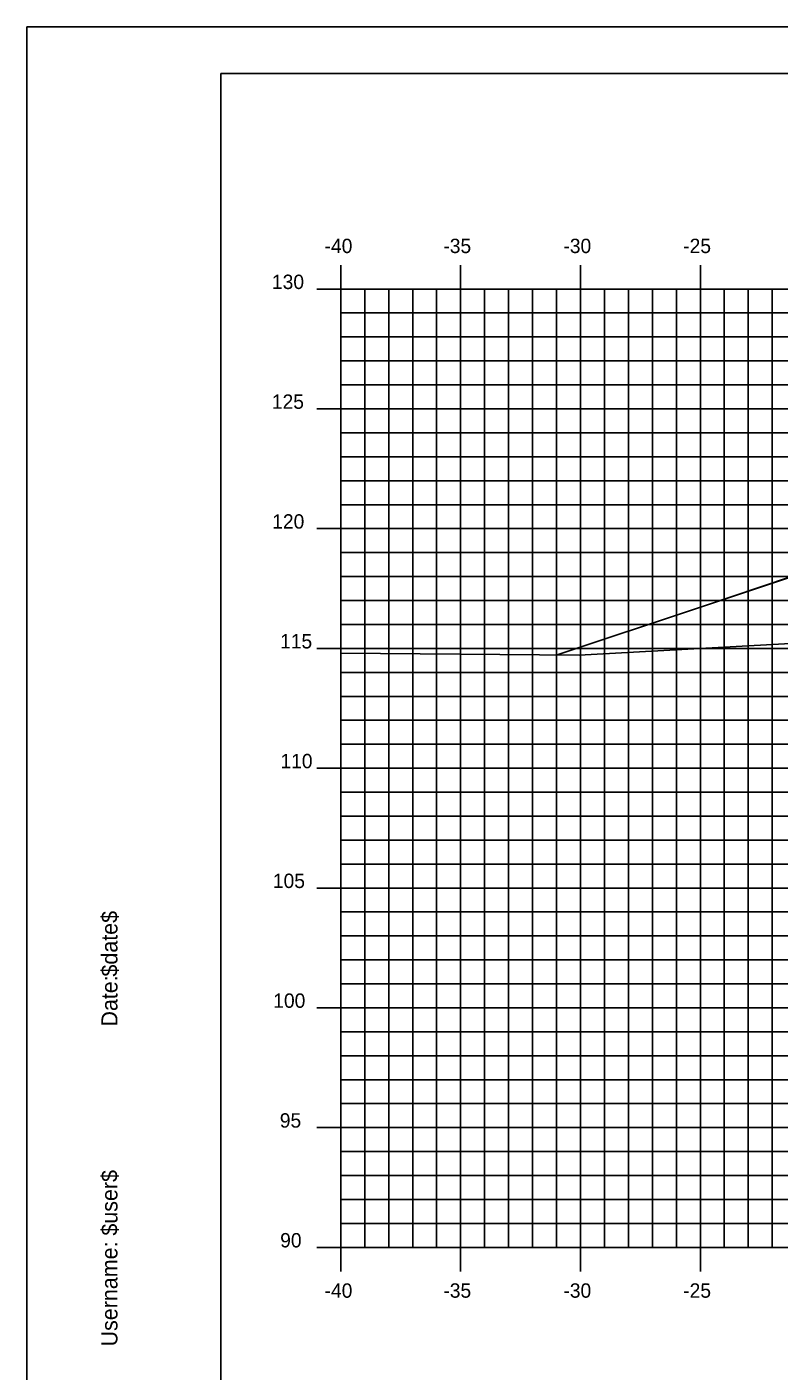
# Model space of a CAD drawing. Extents: x 850598 to 870284, y 366541 to 366651.
# Drawn here: x 852371.9 to 852403.2, y 366595.1 to 366651.2 of the extents above; entities that cross this region are included whole.
import ezdxf

# ---------------------------------------------------------------- set-up
doc = ezdxf.new("R2010")
doc.units = 0
for name, color, linetype in [('BORDER', 7, 'Continuous'), ('D_Roadway_Centerline', 7, 'Continuous'), ('D_Roadway_SlopeLines', 7, 'Continuous'), ('H_V ANNOTATION', 7, 'Continuous'), ('MAJOR', 7, 'Continuous'), ('MINOR', 7, 'Continuous'), ('PLOT BOUNDARY', 7, 'Continuous'), ('S_Roadway_Centerline', 7, 'Continuous')]:
    doc.layers.add(name, color=color, linetype=linetype)

msp = doc.modelspace()

# ---------------------------------------------------------------- linework, layer by layer
at = {"layer": 'BORDER'}
for p, q in [((852539.949, 366649.225), (852379.949, 366649.225)), ((852379.949, 366649.225), (852379.949, 366544.225))]:
    msp.add_line(p, q, dxfattribs=at)
at = {"layer": 'D_Roadway_Centerline'}
msp.add_lwpolyline([(852393.929, 366624.947), (852399.949, 366626.954), (852403.751, 366628.221), (852409.949, 366630.287), (852413.949, 366630.527), (852424.949, 366630.857), (852435.949, 366630.527), (852439.949, 366630.287), (852441.949, 366630.167), (852447.949, 366628.167), (852483.719, 366618.225), (852495.444, 366614.966), (852505.306, 366612.225), (852509.306, 366612.225)], dxfattribs=at)
at = {"layer": 'D_Roadway_SlopeLines'}
for points in [[(852413.949, 366630.527), (852409.949, 366630.287), (852399.949, 366626.954)], [(852399.949, 366626.954), (852393.929, 366624.947)]]:
    msp.add_lwpolyline(points, dxfattribs=at)
at = {"layer": 'MAJOR'}
for p, q in [((852384.949, 366641.227), (852384.949, 366640.225)), ((852384.949, 366641.227), (852384.949, 366640.225)), ((852389.949, 366641.227), (852389.949, 366640.225)), ((852389.949, 366641.227), (852389.949, 366640.225)), ((852394.949, 366641.227), (852394.949, 366640.225)), ((852394.949, 366641.227), (852394.949, 366640.225)), ((852399.949, 366641.227), (852399.949, 366640.225)), ((852399.949, 366641.227), (852399.949, 366640.225)), ((852383.947, 366640.225), (852384.949, 366640.225)), ((852383.947, 366640.225), (852384.949, 366640.225)), ((852384.949, 366640.225), (852524.949, 366640.225)), ((852384.949, 366600.225), (852384.949, 366640.225)), ((852384.949, 366600.225), (852384.949, 366640.225)), ((852384.949, 366640.225), (852524.949, 366640.225)), ((852384.949, 366640.225), (852524.949, 366640.225)), ((852384.949, 366600.225), (852384.949, 366640.225)), ((852384.949, 366600.225), (852384.949, 366640.225)), ((852384.949, 366640.225), (852524.949, 366640.225)), ((852389.949, 366600.225), (852389.949, 366640.225)), ((852389.949, 366600.225), (852389.949, 366640.225)), ((852394.949, 366600.225), (852394.949, 366640.225)), ((852394.949, 366600.225), (852394.949, 366640.225)), ((852399.949, 366600.225), (852399.949, 366640.225)), ((852399.949, 366600.225), (852399.949, 366640.225)), ((852383.947, 366635.225), (852384.949, 366635.225)), ((852383.947, 366635.225), (852384.949, 366635.225)), ((852384.949, 366635.225), (852524.949, 366635.225)), ((852384.949, 366635.225), (852524.949, 366635.225)), ((852383.947, 366630.225), (852384.949, 366630.225)), ((852383.947, 366630.225), (852384.949, 366630.225)), ((852384.949, 366630.225), (852524.949, 366630.225)), ((852384.949, 366630.225), (852524.949, 366630.225)), ((852383.947, 366625.225), (852384.949, 366625.225)), ((852383.947, 366625.225), (852384.949, 366625.225)), ((852384.949, 366625.225), (852524.949, 366625.225)), ((852384.949, 366625.225), (852524.949, 366625.225)), ((852383.947, 366620.225), (852384.949, 366620.225)), ((852383.947, 366620.225), (852384.949, 366620.225)), ((852384.949, 366620.225), (852524.949, 366620.225)), ((852384.949, 366620.225), (852524.949, 366620.225)), ((852383.947, 366615.225), (852384.949, 366615.225)), ((852383.947, 366615.225), (852384.949, 366615.225)), ((852384.949, 366615.225), (852524.949, 366615.225)), ((852384.949, 366615.225), (852524.949, 366615.225)), ((852383.947, 366610.225), (852384.949, 366610.225)), ((852383.947, 366610.225), (852384.949, 366610.225)), ((852384.949, 366610.225), (852524.949, 366610.225)), ((852384.949, 366610.225), (852524.949, 366610.225)), ((852383.947, 366605.225), (852384.949, 366605.225)), ((852383.947, 366605.225), (852384.949, 366605.225)), ((852384.949, 366605.225), (852524.949, 366605.225)), ((852384.949, 366605.225), (852524.949, 366605.225)), ((852383.947, 366600.225), (852384.949, 366600.225)), ((852383.947, 366600.225), (852384.949, 366600.225)), ((852384.949, 366600.225), (852524.949, 366600.225)), ((852384.949, 366600.225), (852524.949, 366600.225)), ((852384.949, 366599.223), (852384.949, 366600.225)), ((852384.949, 366600.225), (852524.949, 366600.225)), ((852384.949, 366600.225), (852524.949, 366600.225)), ((852384.949, 366599.223), (852384.949, 366600.225)), ((852389.949, 366599.223), (852389.949, 366600.225)), ((852389.949, 366599.223), (852389.949, 366600.225)), ((852394.949, 366599.223), (852394.949, 366600.225)), ((852394.949, 366599.223), (852394.949, 366600.225)), ((852399.949, 366599.223), (852399.949, 366600.225)), ((852399.949, 366599.223), (852399.949, 366600.225))]:
    msp.add_line(p, q, dxfattribs=at)
at = {"layer": 'MINOR'}
for p, q in [((852385.949, 366600.225), (852385.949, 366640.225)), ((852385.949, 366600.225), (852385.949, 366640.225)), ((852386.949, 366600.225), (852386.949, 366640.225)), ((852386.949, 366600.225), (852386.949, 366640.225)), ((852387.949, 366600.225), (852387.949, 366640.225)), ((852387.949, 366600.225), (852387.949, 366640.225)), ((852388.949, 366600.225), (852388.949, 366640.225)), ((852388.949, 366600.225), (852388.949, 366640.225)), ((852390.949, 366600.225), (852390.949, 366640.225)), ((852390.949, 366600.225), (852390.949, 366640.225)), ((852391.949, 366600.225), (852391.949, 366640.225)), ((852391.949, 366600.225), (852391.949, 366640.225)), ((852392.949, 366600.225), (852392.949, 366640.225)), ((852392.949, 366600.225), (852392.949, 366640.225)), ((852393.949, 366600.225), (852393.949, 366640.225)), ((852393.949, 366600.225), (852393.949, 366640.225)), ((852395.949, 366600.225), (852395.949, 366640.225)), ((852395.949, 366600.225), (852395.949, 366640.225)), ((852396.949, 366600.225), (852396.949, 366640.225)), ((852396.949, 366600.225), (852396.949, 366640.225)), ((852397.949, 366600.225), (852397.949, 366640.225)), ((852397.949, 366600.225), (852397.949, 366640.225)), ((852398.949, 366600.225), (852398.949, 366640.225)), ((852398.949, 366600.225), (852398.949, 366640.225)), ((852400.949, 366600.225), (852400.949, 366640.225)), ((852400.949, 366600.225), (852400.949, 366640.225)), ((852401.949, 366600.225), (852401.949, 366640.225)), ((852401.949, 366600.225), (852401.949, 366640.225)), ((852402.949, 366600.225), (852402.949, 366640.225)), ((852402.949, 366600.225), (852402.949, 366640.225)), ((852384.949, 366639.225), (852524.949, 366639.225)), ((852384.949, 366639.225), (852385.951, 366639.225)), ((852384.949, 366639.225), (852524.949, 366639.225)), ((852384.949, 366639.225), (852385.951, 366639.225)), ((852384.949, 366638.225), (852524.949, 366638.225)), ((852384.949, 366638.225), (852385.951, 366638.225)), ((852384.949, 366638.225), (852524.949, 366638.225)), ((852384.949, 366638.225), (852385.951, 366638.225)), ((852384.949, 366637.225), (852524.949, 366637.225)), ((852384.949, 366637.225), (852385.951, 366637.225)), ((852384.949, 366637.225), (852524.949, 366637.225)), ((852384.949, 366637.225), (852385.951, 366637.225)), ((852384.949, 366636.225), (852524.949, 366636.225)), ((852384.949, 366636.225), (852385.951, 366636.225)), ((852384.949, 366636.225), (852524.949, 366636.225)), ((852384.949, 366636.225), (852385.951, 366636.225)), ((852384.949, 366634.225), (852524.949, 366634.225)), ((852384.949, 366634.225), (852385.951, 366634.225)), ((852384.949, 366634.225), (852524.949, 366634.225)), ((852384.949, 366634.225), (852385.951, 366634.225)), ((852384.949, 366633.225), (852524.949, 366633.225)), ((852384.949, 366633.225), (852385.951, 366633.225)), ((852384.949, 366633.225), (852524.949, 366633.225)), ((852384.949, 366633.225), (852385.951, 366633.225)), ((852384.949, 366632.225), (852524.949, 366632.225)), ((852384.949, 366632.225), (852385.951, 366632.225)), ((852384.949, 366632.225), (852524.949, 366632.225)), ((852384.949, 366632.225), (852385.951, 366632.225)), ((852384.949, 366631.225), (852524.949, 366631.225)), ((852384.949, 366631.225), (852385.951, 366631.225)), ((852384.949, 366631.225), (852524.949, 366631.225)), ((852384.949, 366631.225), (852385.951, 366631.225)), ((852384.949, 366629.225), (852524.949, 366629.225)), ((852384.949, 366629.225), (852385.951, 366629.225)), ((852384.949, 366629.225), (852524.949, 366629.225)), ((852384.949, 366629.225), (852385.951, 366629.225)), ((852384.949, 366628.225), (852524.949, 366628.225)), ((852384.949, 366628.225), (852385.951, 366628.225)), ((852384.949, 366628.225), (852524.949, 366628.225)), ((852384.949, 366628.225), (852385.951, 366628.225)), ((852384.949, 366627.225), (852524.949, 366627.225)), ((852384.949, 366627.225), (852385.951, 366627.225)), ((852384.949, 366627.225), (852524.949, 366627.225)), ((852384.949, 366627.225), (852385.951, 366627.225)), ((852384.949, 366626.225), (852524.949, 366626.225)), ((852384.949, 366626.225), (852385.951, 366626.225)), ((852384.949, 366626.225), (852524.949, 366626.225)), ((852384.949, 366626.225), (852385.951, 366626.225)), ((852384.949, 366624.225), (852524.949, 366624.225)), ((852384.949, 366624.225), (852385.951, 366624.225)), ((852384.949, 366624.225), (852524.949, 366624.225)), ((852384.949, 366624.225), (852385.951, 366624.225)), ((852384.949, 366623.225), (852524.949, 366623.225)), ((852384.949, 366623.225), (852385.951, 366623.225)), ((852384.949, 366623.225), (852524.949, 366623.225)), ((852384.949, 366623.225), (852385.951, 366623.225)), ((852384.949, 366622.225), (852524.949, 366622.225)), ((852384.949, 366622.225), (852385.951, 366622.225)), ((852384.949, 366622.225), (852524.949, 366622.225)), ((852384.949, 366622.225), (852385.951, 366622.225)), ((852384.949, 366621.225), (852524.949, 366621.225)), ((852384.949, 366621.225), (852385.951, 366621.225)), ((852384.949, 366621.225), (852524.949, 366621.225)), ((852384.949, 366621.225), (852385.951, 366621.225)), ((852384.949, 366619.225), (852524.949, 366619.225)), ((852384.949, 366619.225), (852385.951, 366619.225)), ((852384.949, 366619.225), (852524.949, 366619.225)), ((852384.949, 366619.225), (852385.951, 366619.225)), ((852384.949, 366618.225), (852524.949, 366618.225)), ((852384.949, 366618.225), (852385.951, 366618.225)), ((852384.949, 366618.225), (852524.949, 366618.225)), ((852384.949, 366618.225), (852385.951, 366618.225)), ((852384.949, 366617.225), (852524.949, 366617.225)), ((852384.949, 366617.225), (852385.951, 366617.225)), ((852384.949, 366617.225), (852524.949, 366617.225)), ((852384.949, 366617.225), (852385.951, 366617.225)), ((852384.949, 366616.225), (852524.949, 366616.225)), ((852384.949, 366616.225), (852385.951, 366616.225)), ((852384.949, 366616.225), (852524.949, 366616.225)), ((852384.949, 366616.225), (852385.951, 366616.225)), ((852384.949, 366614.225), (852524.949, 366614.225)), ((852384.949, 366614.225), (852385.951, 366614.225)), ((852384.949, 366614.225), (852524.949, 366614.225)), ((852384.949, 366614.225), (852385.951, 366614.225)), ((852384.949, 366613.225), (852524.949, 366613.225)), ((852384.949, 366613.225), (852385.951, 366613.225)), ((852384.949, 366613.225), (852524.949, 366613.225)), ((852384.949, 366613.225), (852385.951, 366613.225)), ((852384.949, 366612.225), (852524.949, 366612.225)), ((852384.949, 366612.225), (852385.951, 366612.225)), ((852384.949, 366612.225), (852524.949, 366612.225)), ((852384.949, 366612.225), (852385.951, 366612.225)), ((852384.949, 366611.225), (852524.949, 366611.225)), ((852384.949, 366611.225), (852385.951, 366611.225)), ((852384.949, 366611.225), (852524.949, 366611.225)), ((852384.949, 366611.225), (852385.951, 366611.225)), ((852384.949, 366609.225), (852524.949, 366609.225)), ((852384.949, 366609.225), (852385.951, 366609.225)), ((852384.949, 366609.225), (852524.949, 366609.225)), ((852384.949, 366609.225), (852385.951, 366609.225)), ((852384.949, 366608.225), (852524.949, 366608.225)), ((852384.949, 366608.225), (852385.951, 366608.225)), ((852384.949, 366608.225), (852524.949, 366608.225)), ((852384.949, 366608.225), (852385.951, 366608.225)), ((852384.949, 366607.225), (852524.949, 366607.225)), ((852384.949, 366607.225), (852385.951, 366607.225)), ((852384.949, 366607.225), (852524.949, 366607.225)), ((852384.949, 366607.225), (852385.951, 366607.225)), ((852384.949, 366606.225), (852524.949, 366606.225)), ((852384.949, 366606.225), (852385.951, 366606.225)), ((852384.949, 366606.225), (852524.949, 366606.225)), ((852384.949, 366606.225), (852385.951, 366606.225)), ((852384.949, 366604.225), (852524.949, 366604.225)), ((852384.949, 366604.225), (852385.951, 366604.225)), ((852384.949, 366604.225), (852524.949, 366604.225)), ((852384.949, 366604.225), (852385.951, 366604.225)), ((852384.949, 366603.225), (852524.949, 366603.225)), ((852384.949, 366603.225), (852385.951, 366603.225)), ((852384.949, 366603.225), (852524.949, 366603.225)), ((852384.949, 366603.225), (852385.951, 366603.225)), ((852384.949, 366602.225), (852524.949, 366602.225)), ((852384.949, 366602.225), (852385.951, 366602.225)), ((852384.949, 366602.225), (852524.949, 366602.225)), ((852384.949, 366602.225), (852385.951, 366602.225)), ((852384.949, 366601.225), (852524.949, 366601.225)), ((852384.949, 366601.225), (852385.951, 366601.225)), ((852384.949, 366601.225), (852524.949, 366601.225)), ((852384.949, 366601.225), (852385.951, 366601.225))]:
    msp.add_line(p, q, dxfattribs=at)
at = {"layer": 'PLOT BOUNDARY'}
msp.add_lwpolyline([(852371.856, 366541.166), (852541.856, 366541.166), (852541.856, 366651.166), (852371.856, 366651.166)], close=True, dxfattribs=at)
at = {"layer": 'S_Roadway_Centerline'}
msp.add_lwpolyline([(852384.949, 366625.021), (852394.894, 366624.939), (852433.439, 366627.075), (852436.917, 366627.272), (852437.77, 366627.366), (852447.867, 366628.721), (852450.904, 366628.911), (852451.195, 366628.952), (852464.7, 366629.715), (852466.098, 366629.797), (852467.593, 366629.799), (852482.117, 366629.802), (852483.666, 366629.225), (852486.144, 366628.273), (852494.557, 366621.501), (852501.114, 366616.402), (852519.123, 366607.219), (852522.599, 366605.716), (852524.915, 366605.525), (852524.949, 366605.522)], dxfattribs=at)

# ---------------------------------------------------------------- texts
at = {"layer": 'BORDER'}
for s, p in [('$date$', (852375.634, 366611.53)), ('Date:', (852375.634, 366609.442)), ('$user$', (852375.634, 366600.717)), ('Username:', (852375.634, 366596.093))]:
    msp.add_text(s, height=0.6696, rotation=90, dxfattribs=at).set_placement(p)
at = {"layer": 'H_V ANNOTATION'}
for s, p in [('-40', (852384.275, 366641.725)), ('-35', (852389.229, 366641.725)), ('-30', (852394.237, 366641.725)), ('-25', (852399.235, 366641.725)), ('130', (852382.079, 366640.225)), ('125', (852382.074, 366635.225)), ('120', (852382.09, 366630.225)), ('115', (852382.417, 366625.225)), ('110', (852382.433, 366620.225)), ('105', (852382.117, 366615.225)), ('100', (852382.133, 366610.225)), ('95', (852382.406, 366605.225)), ('90', (852382.422, 366600.225)), ('-40', (852384.275, 366598.125)), ('-35', (852389.229, 366598.125)), ('-30', (852394.237, 366598.125)), ('-25', (852399.235, 366598.125))]:
    msp.add_text(s, height=0.6, dxfattribs=at).set_placement(p)

doc.saveas('drawing.dxf')
